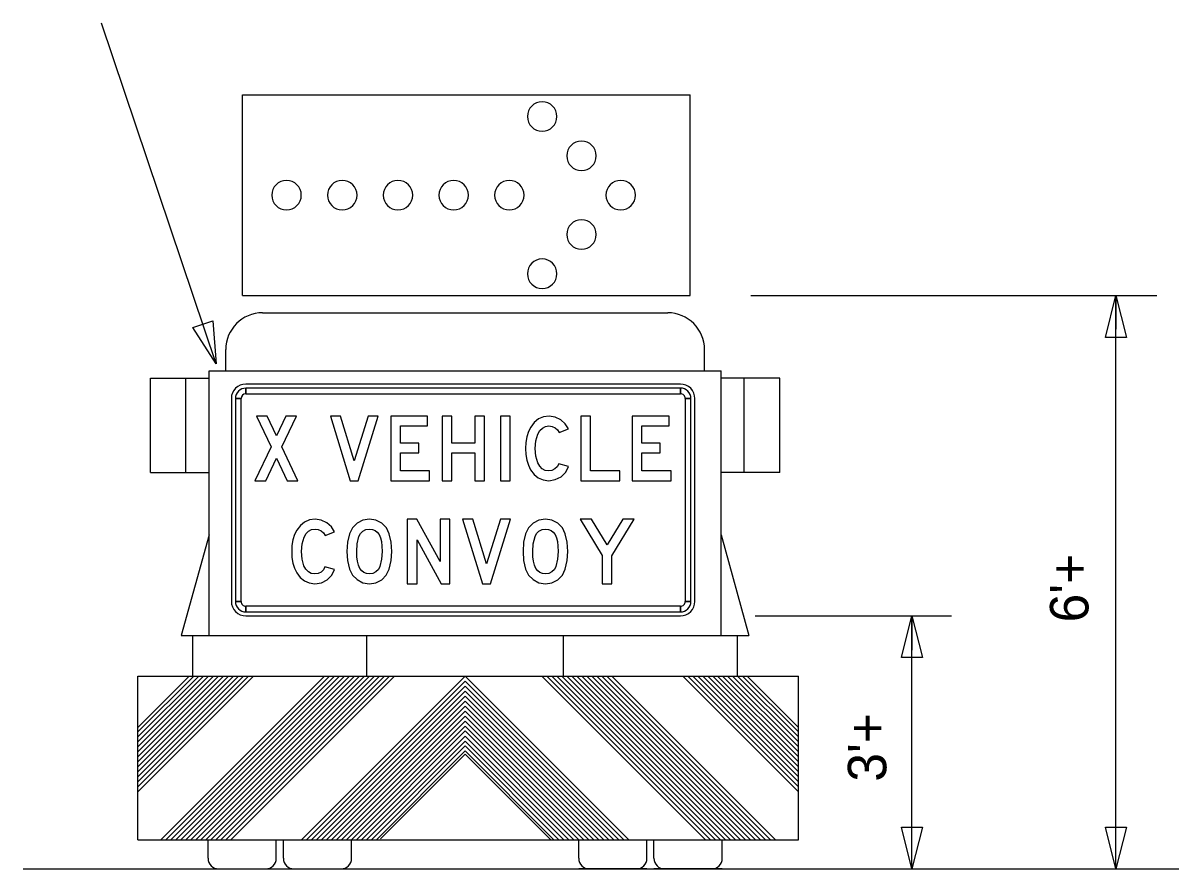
# Model space of a CAD drawing. Extents: x 1806907 to 1812607, y 675071 to 676228.
# Drawn here: x 1811793.7 to 1811973.8, y 675887.7 to 676019.5 of the extents above; entities that cross this region are included whole.
import ezdxf

# ---------------------------------------------------------------- set-up
doc = ezdxf.new("R2010")
doc.units = 0
doc.layers.add('Working Level 1', color=7, linetype='Continuous')

msp = doc.modelspace()

# ---------------------------------------------------------------- linework, layer by layer
at = {"layer": 'Working Level 1'}
for p, q in [((1811823.74, 675966.4), (1811805.89, 676019.47)), ((1811827.84, 676008.3), (1811897.61, 676008.3)), ((1811827.84, 675977.01), (1811827.84, 676008.3)), ((1811897.61, 675977.01), (1811897.61, 676008.3)), ((1811827.84, 675977.01), (1811897.61, 675977.01)), ((1811907.08, 675977.01), (1811970.35, 675977.01)), ((1811963.98, 675887.7), (1811963.98, 675977.01)), ((1811963.98, 675977.01), (1811963.98, 675971.77)), ((1811830.98, 675974.33), (1811894.12, 675974.33)), ((1811825.24, 675965.3), (1811825.24, 675968.6)), ((1811899.87, 675965.3), (1811899.87, 675968.6)), ((1811822.64, 675924.04), (1811822.64, 675965.3)), ((1811822.64, 675965.3), (1811902.47, 675965.3)), ((1811902.47, 675924.04), (1811902.47, 675965.3)), ((1811813.53, 675949.47), (1811813.53, 675964.14)), ((1811813.53, 675964.14), (1811822.64, 675964.14)), ((1811819.05, 675949.47), (1811819.05, 675964.14)), ((1811896.1, 675963.23), (1811828.38, 675963.23)), ((1811911.58, 675964.14), (1811902.47, 675964.14)), ((1811906.06, 675949.47), (1811906.06, 675964.14)), ((1811911.58, 675949.47), (1811911.58, 675964.14)), ((1811826.13, 675960.97), (1811826.13, 675929.37)), ((1811826.75, 675960.97), (1811827.63, 675960.97)), ((1811828.38, 675961.73), (1811828.38, 675962.6)), ((1811896.1, 675962.6), (1811896.1, 675961.73)), ((1811896.85, 675960.97), (1811897.73, 675960.97)), ((1811898.35, 675929.37), (1811898.35, 675960.97)), ((1811813.53, 675949.47), (1811822.64, 675949.47)), ((1811911.58, 675949.47), (1811902.47, 675949.47)), ((1811822.64, 675939.76), (1811818.32, 675924.04)), ((1811902.47, 675939.76), (1811906.78, 675924.04)), ((1811827.63, 675929.37), (1811826.75, 675929.37)), ((1811828.38, 675927.74), (1811828.38, 675928.62)), ((1811896.1, 675928.62), (1811896.1, 675927.74)), ((1811897.73, 675929.37), (1811896.85, 675929.37)), ((1811828.38, 675927.12), (1811896.1, 675927.12)), ((1811907.73, 675927.12), (1811938.35, 675927.12)), ((1811932.17, 675887.7), (1811932.17, 675927.12)), ((1811932.17, 675927.12), (1811932.17, 675921.79)), ((1811818.32, 675924.04), (1811906.78, 675924.04)), ((1811820.12, 675917.73), (1811820.12, 675924.04)), ((1811847.24, 675917.73), (1811847.24, 675923.92)), ((1811877.87, 675917.73), (1811877.87, 675923.92)), ((1811904.99, 675917.73), (1811904.99, 675924.04)), ((1811811.55, 675917.73), (1811914.5, 675917.73)), ((1811811.55, 675917.73), (1811914.5, 675917.73)), ((1811811.55, 675917.73), (1811914.5, 675917.73)), ((1811811.55, 675917.73), (1811914.5, 675917.73)), ((1811811.55, 675892.24), (1811811.55, 675917.73)), ((1811811.55, 675909.75), (1811819.53, 675917.73)), ((1811811.55, 675900.47), (1811828.81, 675917.73)), ((1811811.55, 675901.26), (1811828.02, 675917.73)), ((1811811.55, 675902.04), (1811827.24, 675917.73)), ((1811811.55, 675902.81), (1811826.47, 675917.73)), ((1811811.55, 675903.59), (1811825.69, 675917.73)), ((1811811.55, 675904.37), (1811824.91, 675917.73)), ((1811811.55, 675905.14), (1811824.14, 675917.73)), ((1811811.55, 675905.92), (1811823.36, 675917.73)), ((1811811.55, 675906.7), (1811822.58, 675917.73)), ((1811811.55, 675907.48), (1811821.8, 675917.73)), ((1811811.55, 675908.25), (1811821.03, 675917.73)), ((1811811.55, 675909.03), (1811820.25, 675917.73)), ((1811811.55, 675899.7), (1811829.56, 675917.71)), ((1811815.14, 675892.24), (1811840.64, 675917.73)), ((1811815.91, 675892.24), (1811841.41, 675917.73)), ((1811816.69, 675892.24), (1811842.19, 675917.73)), ((1811817.48, 675892.24), (1811842.97, 675917.73)), ((1811818.25, 675892.24), (1811843.74, 675917.73)), ((1811819.03, 675892.24), (1811844.52, 675917.73)), ((1811819.81, 675892.24), (1811845.31, 675917.73)), ((1811820.59, 675892.24), (1811846.09, 675917.73)), ((1811821.36, 675892.24), (1811846.86, 675917.73)), ((1811822.14, 675892.24), (1811847.64, 675917.73)), ((1811822.92, 675892.24), (1811848.42, 675917.73)), ((1811823.69, 675892.24), (1811849.19, 675917.73)), ((1811824.47, 675892.24), (1811849.97, 675917.73)), ((1811825.25, 675892.24), (1811850.74, 675917.72)), ((1811826.03, 675892.24), (1811851.53, 675917.73)), ((1811837.06, 675892.24), (1811862.55, 675917.73)), ((1811888.05, 675892.24), (1811862.55, 675917.73)), ((1811900.01, 675892.24), (1811874.52, 675917.73)), ((1811900.79, 675892.24), (1811875.3, 675917.72)), ((1811901.57, 675892.24), (1811876.07, 675917.73)), ((1811902.35, 675892.24), (1811876.85, 675917.73)), ((1811903.12, 675892.24), (1811877.62, 675917.73)), ((1811903.9, 675892.24), (1811878.4, 675917.73)), ((1811904.68, 675892.24), (1811879.19, 675917.73)), ((1811905.45, 675892.24), (1811879.96, 675917.73)), ((1811906.23, 675892.24), (1811880.74, 675917.73)), ((1811907.02, 675892.24), (1811881.52, 675917.73)), ((1811907.8, 675892.24), (1811882.3, 675917.73)), ((1811908.57, 675892.24), (1811883.07, 675917.73)), ((1811909.35, 675892.24), (1811883.85, 675917.73)), ((1811910.13, 675892.24), (1811884.63, 675917.73)), ((1811910.9, 675892.24), (1811885.41, 675917.73)), ((1811914.5, 675899.7), (1811896.48, 675917.71)), ((1811914.5, 675900.47), (1811897.24, 675917.73)), ((1811914.5, 675901.26), (1811898.02, 675917.73)), ((1811914.5, 675902.04), (1811898.8, 675917.73)), ((1811914.5, 675902.81), (1811899.57, 675917.73)), ((1811914.5, 675903.59), (1811900.35, 675917.73)), ((1811914.5, 675904.37), (1811901.13, 675917.73)), ((1811914.5, 675905.14), (1811901.9, 675917.73)), ((1811914.5, 675905.92), (1811902.68, 675917.73)), ((1811914.5, 675906.7), (1811903.46, 675917.73)), ((1811914.5, 675907.48), (1811904.24, 675917.73)), ((1811914.5, 675908.25), (1811905.01, 675917.73)), ((1811914.5, 675909.03), (1811905.79, 675917.73)), ((1811914.5, 675909.75), (1811906.52, 675917.73)), ((1811914.5, 675892.24), (1811914.5, 675917.73)), ((1811837.83, 675892.24), (1811862.55, 675916.96)), ((1811838.61, 675892.24), (1811862.55, 675916.18)), ((1811887.24, 675892.28), (1811862.55, 675916.96)), ((1811886.5, 675892.24), (1811862.55, 675916.18)), ((1811839.39, 675892.24), (1811862.55, 675915.4)), ((1811840.16, 675892.24), (1811862.55, 675914.63)), ((1811885.72, 675892.24), (1811862.55, 675915.4)), ((1811884.95, 675892.24), (1811862.55, 675914.63)), ((1811840.94, 675892.24), (1811862.55, 675913.84)), ((1811841.73, 675892.24), (1811862.55, 675913.06)), ((1811842.5, 675892.24), (1811862.55, 675912.29)), ((1811884.17, 675892.24), (1811862.55, 675913.84)), ((1811883.39, 675892.24), (1811862.55, 675913.06)), ((1811882.62, 675892.24), (1811862.55, 675912.29)), ((1811843.28, 675892.24), (1811862.55, 675911.51)), ((1811844.06, 675892.24), (1811862.55, 675910.73)), ((1811881.84, 675892.24), (1811862.55, 675911.51)), ((1811881.06, 675892.24), (1811862.55, 675910.73)), ((1811844.84, 675892.24), (1811862.55, 675909.95)), ((1811845.61, 675892.24), (1811862.55, 675909.18)), ((1811880.27, 675892.24), (1811862.55, 675909.95)), ((1811879.5, 675892.24), (1811862.55, 675909.18)), ((1811846.39, 675892.24), (1811862.55, 675908.4)), ((1811847.17, 675892.24), (1811862.55, 675907.62)), ((1811847.94, 675892.24), (1811862.55, 675906.85)), ((1811878.72, 675892.24), (1811862.55, 675908.4)), ((1811877.94, 675892.24), (1811862.55, 675907.62)), ((1811877.17, 675892.24), (1811862.55, 675906.85)), ((1811848.72, 675892.24), (1811862.55, 675906.07)), ((1811849.37, 675892.38), (1811862.55, 675905.57)), ((1811876.39, 675892.24), (1811862.55, 675906.07)), ((1811875.89, 675892.24), (1811862.55, 675905.57)), ((1811811.55, 675892.24), (1811914.5, 675892.24)), ((1811811.55, 675892.24), (1811914.5, 675892.24)), ((1811811.55, 675892.24), (1811914.5, 675892.24)), ((1811811.55, 675892.24), (1811914.5, 675892.24)), ((1811822.49, 675889.35), (1811822.49, 675892.24)), ((1811833.12, 675889.35), (1811833.12, 675892.24)), ((1811834.22, 675889.35), (1811834.22, 675892.24)), ((1811844.86, 675889.35), (1811844.86, 675892.24)), ((1811880.25, 675889.35), (1811880.25, 675892.24)), ((1811890.88, 675889.35), (1811890.88, 675892.24)), ((1811891.98, 675889.35), (1811891.98, 675892.24)), ((1811902.62, 675889.35), (1811902.62, 675892.24)), ((1811793.67, 675887.7), (1811973.78, 675887.7)), ((1811822.49, 675887.7), (1811833.12, 675887.7)), ((1811822.49, 675887.7), (1811833.12, 675887.7)), ((1811822.49, 675887.7), (1811833.12, 675887.7)), ((1811822.49, 675887.7), (1811833.12, 675887.7)), ((1811834.22, 675887.7), (1811844.86, 675887.7)), ((1811834.22, 675887.7), (1811844.86, 675887.7)), ((1811834.22, 675887.7), (1811844.86, 675887.7)), ((1811834.22, 675887.7), (1811844.86, 675887.7)), ((1811890.88, 675887.7), (1811880.25, 675887.7)), ((1811890.88, 675887.7), (1811880.25, 675887.7)), ((1811890.88, 675887.7), (1811880.25, 675887.7)), ((1811890.88, 675887.7), (1811880.25, 675887.7)), ((1811902.62, 675887.7), (1811891.98, 675887.7)), ((1811902.62, 675887.7), (1811891.98, 675887.7)), ((1811902.62, 675887.7), (1811891.98, 675887.7)), ((1811902.62, 675887.7), (1811891.98, 675887.7))]:
    msp.add_line(p, q, dxfattribs=at)
for points in [[(1811962.36, 675970.51), (1811963.98, 675977.01), (1811965.61, 675970.51)], [(1811823.21, 675973.08), (1811823.74, 675966.4), (1811820.13, 675972.04)], [(1811826.75, 675960.97), (1811826.75, 675929.37), (1811827.63, 675929.37), (1811827.63, 675960.97), (1811826.75, 675960.97)], [(1811896.1, 675962.6), (1811828.38, 675962.6), (1811828.38, 675961.73), (1811896.1, 675961.73), (1811896.1, 675962.6)], [(1811897.73, 675929.37), (1811897.73, 675960.97), (1811896.85, 675960.97), (1811896.85, 675929.37), (1811897.73, 675929.37)], [(1811836.49, 675948.18), (1811833.99, 675953.44), (1811836.28, 675958.21), (1811834.61, 675958.21), (1811833.15, 675955.19), (1811831.71, 675958.21), (1811830.03, 675958.21), (1811832.31, 675953.43), (1811829.79, 675948.18), (1811831.47, 675948.18), (1811833.14, 675951.67), (1811834.81, 675948.18)], [(1811849.02, 675958.21), (1811847.44, 675958.21), (1811845.28, 675951.28), (1811843.13, 675958.21), (1811841.55, 675958.21), (1811844.66, 675948.18), (1811845.9, 675948.18)], [(1811857.02, 675949.7), (1811852.47, 675949.7), (1811852.47, 675952.54), (1811855.31, 675952.54), (1811855.31, 675954.05), (1811852.47, 675954.05), (1811852.47, 675956.7), (1811856.71, 675956.7), (1811856.71, 675958.21), (1811850.95, 675958.21), (1811850.95, 675948.18), (1811857.02, 675948.18)], [(1811865.57, 675948.18), (1811865.57, 675958.21), (1811864.06, 675958.21), (1811864.06, 675954.05), (1811860.46, 675954.05), (1811860.46, 675958.21), (1811858.95, 675958.21), (1811858.95, 675948.18), (1811860.46, 675948.18), (1811860.46, 675952.54), (1811864.06, 675952.54), (1811864.06, 675948.18)], [(1811869.55, 675948.18), (1811869.55, 675958.21), (1811868.04, 675958.21), (1811868.04, 675948.18)], [(1811878.65, 675950.41), (1811877.14, 675950.79), (1811876.91, 675950.35), (1811876.55, 675950), (1811876.08, 675949.77), (1811875.55, 675949.7), (1811875.03, 675949.78), (1811874.57, 675950.02), (1811874.19, 675950.42), (1811873.88, 675950.97), (1811873.57, 675952), (1811873.47, 675953.2), (1811873.58, 675954.4), (1811873.9, 675955.43), (1811874.21, 675955.99), (1811874.6, 675956.38), (1811875.06, 675956.62), (1811875.6, 675956.7), (1811876.1, 675956.63), (1811876.56, 675956.42), (1811876.94, 675956.09), (1811877.2, 675955.67), (1811878.65, 675956.24), (1811878.16, 675957.05), (1811877.45, 675957.68), (1811876.58, 675958.08), (1811875.63, 675958.21), (1811874.74, 675958.11), (1811873.97, 675957.8), (1811873.31, 675957.27), (1811872.77, 675956.54), (1811872.41, 675955.82), (1811872.16, 675955.02), (1811872.01, 675954.15), (1811871.96, 675953.2), (1811872.01, 675952.26), (1811872.16, 675951.39), (1811872.41, 675950.6), (1811872.76, 675949.87), (1811873.29, 675949.13), (1811873.94, 675948.61), (1811874.7, 675948.29), (1811875.58, 675948.18), (1811876.6, 675948.34), (1811877.51, 675948.8), (1811878.23, 675949.51)], [(1811886.65, 675948.18), (1811886.65, 675949.7), (1811882.09, 675949.7), (1811882.09, 675958.21), (1811880.58, 675958.21), (1811880.58, 675948.18)], [(1811894.64, 675949.7), (1811890.09, 675949.7), (1811890.09, 675952.54), (1811892.93, 675952.54), (1811892.93, 675954.05), (1811890.09, 675954.05), (1811890.09, 675956.7), (1811894.33, 675956.7), (1811894.33, 675958.21), (1811888.58, 675958.21), (1811888.58, 675948.18), (1811894.64, 675948.18)], [(1811842.21, 675934.36), (1811840.69, 675934.74), (1811840.47, 675934.3), (1811840.1, 675933.95), (1811839.63, 675933.72), (1811839.11, 675933.65), (1811838.58, 675933.73), (1811838.13, 675933.97), (1811837.75, 675934.37), (1811837.44, 675934.92), (1811837.13, 675935.95), (1811837.03, 675937.15), (1811837.13, 675938.35), (1811837.45, 675939.38), (1811837.77, 675939.93), (1811838.16, 675940.33), (1811838.62, 675940.57), (1811839.16, 675940.65), (1811839.66, 675940.58), (1811840.12, 675940.37), (1811840.5, 675940.04), (1811840.76, 675939.62), (1811842.21, 675940.19), (1811841.72, 675941), (1811841, 675941.63), (1811840.13, 675942.03), (1811839.18, 675942.16), (1811838.3, 675942.06), (1811837.53, 675941.74), (1811836.87, 675941.22), (1811836.32, 675940.49), (1811835.97, 675939.77), (1811835.72, 675938.97), (1811835.57, 675938.1), (1811835.52, 675937.15), (1811835.56, 675936.21), (1811835.71, 675935.34), (1811835.96, 675934.55), (1811836.31, 675933.82), (1811836.85, 675933.08), (1811837.5, 675932.56), (1811838.26, 675932.24), (1811839.13, 675932.13), (1811840.15, 675932.29), (1811841.07, 675932.75), (1811841.78, 675933.46)], [(1811851.14, 675937.15), (1811851.04, 675938.59), (1811850.73, 675939.92), (1811850.28, 675940.83), (1811849.56, 675941.55), (1811848.65, 675942.01), (1811847.63, 675942.16), (1811846.61, 675942.01), (1811845.71, 675941.55), (1811844.99, 675940.83), (1811844.54, 675939.92), (1811844.24, 675938.58), (1811844.14, 675937.15), (1811844.24, 675935.73), (1811844.54, 675934.39), (1811844.99, 675933.48), (1811845.71, 675932.76), (1811846.61, 675932.29), (1811847.63, 675932.13), (1811848.65, 675932.29), (1811849.55, 675932.75), (1811850.27, 675933.46), (1811850.72, 675934.37), (1811851.03, 675935.72)], [(1811860.17, 675932.13), (1811860.17, 675942.16), (1811858.65, 675942.16), (1811858.65, 675935.57), (1811855, 675942.16), (1811853.54, 675942.16), (1811853.54, 675932.13), (1811855.06, 675932.13), (1811855.06, 675938.94), (1811858.83, 675932.13)], [(1811869.63, 675942.16), (1811868.05, 675942.16), (1811865.89, 675935.23), (1811863.75, 675942.16), (1811862.16, 675942.16), (1811865.27, 675932.13), (1811866.52, 675932.13)], [(1811878.57, 675937.15), (1811878.47, 675938.59), (1811878.16, 675939.92), (1811877.71, 675940.83), (1811876.99, 675941.55), (1811876.08, 675942.01), (1811875.06, 675942.16), (1811874.04, 675942.01), (1811873.14, 675941.55), (1811872.42, 675940.83), (1811871.98, 675939.92), (1811871.67, 675938.58), (1811871.57, 675937.15), (1811871.67, 675935.73), (1811871.98, 675934.39), (1811872.42, 675933.48), (1811873.14, 675932.76), (1811874.04, 675932.29), (1811875.06, 675932.13), (1811876.08, 675932.29), (1811876.99, 675932.75), (1811877.7, 675933.46), (1811878.15, 675934.37), (1811878.46, 675935.72)], [(1811888.91, 675942.16), (1811887.13, 675942.16), (1811884.67, 675938.16), (1811882.26, 675942.16), (1811880.5, 675942.16), (1811883.91, 675936.53), (1811883.91, 675932.13), (1811885.42, 675932.13), (1811885.42, 675936.49)], [(1811849.63, 675937.15), (1811849.54, 675935.93), (1811849.27, 675934.8), (1811849.03, 675934.32), (1811848.65, 675933.96), (1811848.18, 675933.72), (1811847.64, 675933.65), (1811847.17, 675933.7), (1811846.77, 675933.87), (1811846.43, 675934.14), (1811846.15, 675934.52), (1811845.93, 675935.01), (1811845.77, 675935.62), (1811845.68, 675936.33), (1811845.65, 675937.15), (1811845.74, 675938.36), (1811846.01, 675939.49), (1811846.24, 675939.96), (1811846.62, 675940.33), (1811847.1, 675940.57), (1811847.64, 675940.65), (1811848.11, 675940.59), (1811848.51, 675940.43), (1811848.85, 675940.16), (1811849.13, 675939.77), (1811849.34, 675939.28), (1811849.5, 675938.68), (1811849.59, 675937.97)], [(1811877.06, 675937.15), (1811876.97, 675935.93), (1811876.7, 675934.8), (1811876.46, 675934.32), (1811876.08, 675933.96), (1811875.61, 675933.72), (1811875.07, 675933.65), (1811874.6, 675933.7), (1811874.2, 675933.87), (1811873.86, 675934.14), (1811873.58, 675934.52), (1811873.36, 675935.01), (1811873.2, 675935.62), (1811873.11, 675936.33), (1811873.08, 675937.15), (1811873.17, 675938.36), (1811873.44, 675939.49), (1811873.68, 675939.96), (1811874.05, 675940.33), (1811874.53, 675940.57), (1811875.07, 675940.65), (1811875.54, 675940.59), (1811875.94, 675940.43), (1811876.28, 675940.16), (1811876.56, 675939.77), (1811876.77, 675939.28), (1811876.93, 675938.68), (1811877.02, 675937.97)], [(1811828.38, 675927.74), (1811896.1, 675927.74), (1811896.1, 675928.62), (1811828.38, 675928.62), (1811828.38, 675927.74)], [(1811930.55, 675920.62), (1811932.17, 675927.12), (1811933.8, 675920.62)], [(1811933.8, 675894.2), (1811932.17, 675887.7), (1811930.55, 675894.2)], [(1811965.61, 675894.2), (1811963.98, 675887.7), (1811962.36, 675894.2)]]:
    msp.add_lwpolyline(points, close=True, dxfattribs=at)
for centre, radius, start, end in [((1811874.56, 676004.92), 2.3, 0, 180), ((1811874.56, 676004.92), 2.3, 180, 0), ((1811880.68, 675998.79), 2.3, 0, 180), ((1811880.68, 675998.79), 2.3, 180, 0), ((1811834.72, 675992.66), 2.3, 0, 180), ((1811843.4, 675992.66), 2.3, 0, 180), ((1811852.08, 675992.66), 2.3, 0, 180), ((1811860.76, 675992.66), 2.3, 0, 180), ((1811869.44, 675992.66), 2.3, 0, 180), ((1811886.8, 675992.66), 2.3, 0, 180), ((1811834.72, 675992.66), 2.3, 180, 0), ((1811843.4, 675992.66), 2.3, 180, 0), ((1811852.08, 675992.66), 2.3, 180, 0), ((1811860.76, 675992.66), 2.3, 180, 0), ((1811869.44, 675992.66), 2.3, 180, 0), ((1811886.8, 675992.66), 2.3, 180, 0), ((1811880.68, 675986.54), 2.3, 0, 180), ((1811880.68, 675986.54), 2.3, 180, 0), ((1811874.56, 675980.42), 2.3, 0, 180), ((1811874.56, 675980.42), 2.3, 180, 0), ((1811830.98, 675968.6), 5.74, 90, 180), ((1811894.12, 675968.6), 5.74, 0, 90), ((1811828.38, 675960.97), 2.26, 90.0002, 179.9998), ((1811896.1, 675960.97), 2.26, 0, 90.0002), ((1811828.38, 675960.97), 1.63, 90.0002, 179.9998), ((1811828.38, 675960.97), 0.752, 90.0002, 179.9998), ((1811896.1, 675960.97), 1.63, 0, 90.0002), ((1811896.1, 675960.97), 0.752, 0, 90.0002), ((1811828.38, 675929.37), 2.26, 179.9998, 270.0001), ((1811828.38, 675929.37), 1.63, 179.9998, 270.0001), ((1811828.38, 675929.37), 0.752, 179.9998, 270.0001), ((1811896.1, 675929.37), 2.26, 270.0001, 0.0003), ((1811896.1, 675929.37), 1.63, 270.0001, 0.0003), ((1811896.1, 675929.37), 0.752, 270.0001, 0.0003), ((1811824.14, 675889.35), 1.65, 180, 270), ((1811831.47, 675889.35), 1.65, 270, 0), ((1811835.87, 675889.35), 1.65, 180, 270), ((1811843.21, 675889.35), 1.65, 270, 0), ((1811881.9, 675889.35), 1.65, 180, 270), ((1811889.23, 675889.35), 1.65, 270, 0), ((1811893.63, 675889.35), 1.65, 180, 270), ((1811900.97, 675889.35), 1.65, 270, 0)]:
    msp.add_arc(centre, radius, start, end, dxfattribs=at)

# ---------------------------------------------------------------- texts
for s, p in [("6'+", (1811959.69, 675926.1)), ("3'+", (1811928.19, 675901.29))]:
    msp.add_text(s, height=6, rotation=90, dxfattribs=at).set_placement(p)

doc.saveas('drawing.dxf')
